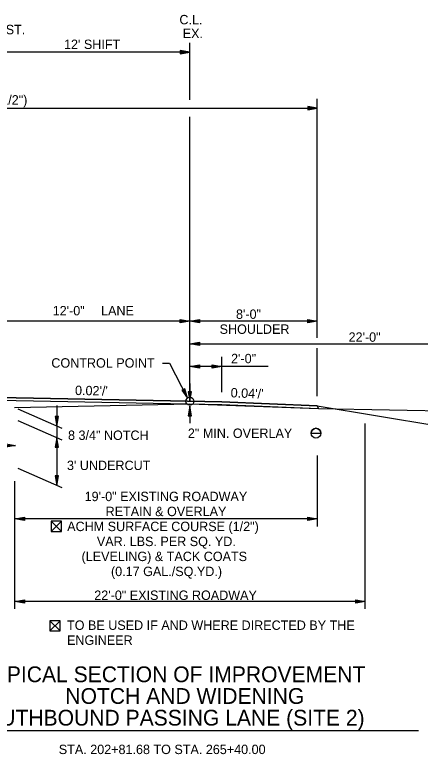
# Model space of a CAD drawing. Extents: x 1398565 to 1398920, y 1968324 to 1968581.
# Drawn here: x 1398642.8 to 1398668.26, y 1968324.76 to 1968371.14 of the extents above; entities that cross this region are included whole.
import ezdxf

# ---------------------------------------------------------------- set-up
doc = ezdxf.new("R2010")
doc.units = 0
for name, color, linetype in [('10', 7, 'Continuous'), ('19', 7, 'Continuous'), ('42', 7, 'Continuous'), ('7', 7, 'Continuous'), ('Level 9', 7, 'Continuous')]:
    doc.layers.add(name, color=color, linetype=linetype)

msp = doc.modelspace()

# ---------------------------------------------------------------- linework, layer by layer
at = {"layer": '10'}
for p, q in [((1398661.408, 1968344.894), (1398662.019, 1968344.894)), ((1398645.093, 1968339.376), (1398645.734, 1968338.735)), ((1398645.734, 1968339.376), (1398645.093, 1968338.735)), ((1398645.474, 1968338.735), (1398645.485, 1968338.735)), ((1398645.011, 1968333.13), (1398645.653, 1968332.489)), ((1398645.653, 1968333.13), (1398645.011, 1968332.489)), ((1398645.393, 1968332.489), (1398645.404, 1968332.489))]:
    msp.add_line(p, q, dxfattribs=at)
for points in [[(1398645.485, 1968338.735), (1398645.734, 1968338.735), (1398645.734, 1968339.376), (1398645.093, 1968339.376), (1398645.093, 1968338.735), (1398645.474, 1968338.735)], [(1398645.404, 1968332.489), (1398645.653, 1968332.489), (1398645.653, 1968333.13), (1398645.011, 1968333.13), (1398645.011, 1968332.489), (1398645.393, 1968332.489)]]:
    msp.add_lwpolyline(points, dxfattribs=at)
msp.add_circle((1398661.713, 1968344.894), 0.306, dxfattribs=at)
msp.add_arc((1398661.713, 1968344.894), 0.306, 0, 180, dxfattribs=at)
at = {"layer": '19'}
for p, q in [((1398653.795, 1968368.786), (1398641.795, 1968368.786)), ((1398653.195, 1968368.891), (1398653.195, 1968368.681)), ((1398653.795, 1968368.786), (1398653.195, 1968368.891)), ((1398653.635, 1968368.801), (1398653.195, 1968368.836)), ((1398653.195, 1968368.681), (1398653.795, 1968368.786)), ((1398653.195, 1968368.731), (1398653.635, 1968368.771)), ((1398661.795, 1968350.874), (1398661.795, 1968365.876)), ((1398611.795, 1968365.276), (1398661.795, 1968365.276)), ((1398661.195, 1968365.381), (1398661.195, 1968365.171)), ((1398661.795, 1968365.276), (1398661.195, 1968365.381)), ((1398661.635, 1968365.291), (1398661.195, 1968365.326)), ((1398661.195, 1968365.171), (1398661.795, 1968365.276)), ((1398661.195, 1968365.221), (1398661.635, 1968365.261)), ((1398653.195, 1968351.816), (1398653.195, 1968352.026)), ((1398653.195, 1968352.026), (1398653.795, 1968351.921)), ((1398653.795, 1968351.921), (1398654.395, 1968352.026)), ((1398654.395, 1968352.026), (1398654.395, 1968351.816)), ((1398661.195, 1968351.816), (1398661.195, 1968352.026)), ((1398661.195, 1968352.026), (1398661.795, 1968351.921)), ((1398643.795, 1968351.921), (1398631.795, 1968351.921)), ((1398661.795, 1968351.921), (1398643.795, 1968351.921)), ((1398653.195, 1968351.971), (1398653.635, 1968351.936)), ((1398653.795, 1968351.921), (1398653.195, 1968351.816)), ((1398653.635, 1968351.906), (1398653.195, 1968351.866)), ((1398654.395, 1968351.816), (1398653.795, 1968351.921)), ((1398653.955, 1968351.936), (1398654.395, 1968351.971)), ((1398654.395, 1968351.866), (1398653.955, 1968351.906)), ((1398661.195, 1968351.971), (1398661.635, 1968351.936)), ((1398661.795, 1968351.921), (1398661.195, 1968351.816)), ((1398661.635, 1968351.906), (1398661.195, 1968351.866)), ((1398653.795, 1968350.5), (1398654.395, 1968350.605)), ((1398654.395, 1968350.605), (1398654.395, 1968350.395)), ((1398653.795, 1968350.5), (1398675.795, 1968350.5)), ((1398654.395, 1968350.395), (1398653.795, 1968350.5)), ((1398653.955, 1968350.515), (1398654.395, 1968350.55)), ((1398654.395, 1968350.445), (1398653.955, 1968350.485)), ((1398661.795, 1968347.218), (1398661.795, 1968350.232)), ((1398655.795, 1968347.458), (1398655.795, 1968349.679)), ((1398653.795, 1968349.079), (1398654.395, 1968349.184)), ((1398658.72, 1968349.079), (1398653.795, 1968349.079)), ((1398654.395, 1968348.974), (1398653.795, 1968349.079)), ((1398653.955, 1968349.094), (1398654.395, 1968349.129)), ((1398654.395, 1968349.024), (1398653.955, 1968349.064)), ((1398654.395, 1968349.184), (1398654.395, 1968348.974)), ((1398655.195, 1968348.974), (1398655.195, 1968349.184)), ((1398655.195, 1968349.184), (1398655.795, 1968349.079)), ((1398655.195, 1968349.129), (1398655.635, 1968349.094)), ((1398655.795, 1968349.079), (1398655.195, 1968348.974)), ((1398655.635, 1968349.064), (1398655.195, 1968349.024)), ((1398653.795, 1968348.006), (1398653.795, 1968346.898)), ((1398653.472, 1968347.683), (1398653.286, 1968347.588)), ((1398653.286, 1968347.588), (1398653.649, 1968347.101)), ((1398653.328, 1968347.606), (1398653.563, 1968347.237)), ((1398653.587, 1968347.247), (1398653.426, 1968347.655)), ((1398653.649, 1968347.101), (1398653.472, 1968347.683)), ((1398653.9, 1968347.498), (1398653.69, 1968347.498)), ((1398653.69, 1968347.498), (1398653.795, 1968346.898)), ((1398653.745, 1968347.498), (1398653.78, 1968347.058)), ((1398653.795, 1968346.898), (1398653.9, 1968347.498)), ((1398653.81, 1968347.058), (1398653.85, 1968347.498)), ((1398641.795, 1968347.138), (1398655.795, 1968346.858)), ((1398641.795, 1968346.971), (1398655.795, 1968346.691)), ((1398643.004, 1968346.419), (1398645.747, 1968345.209)), ((1398645.444, 1968346.621), (1398645.444, 1968345.345)), ((1398653.795, 1968346.585), (1398653.69, 1968345.985)), ((1398653.78, 1968346.425), (1398653.745, 1968345.985)), ((1398653.795, 1968346.611), (1398653.795, 1968345.528)), ((1398653.9, 1968345.985), (1398653.795, 1968346.585)), ((1398653.85, 1968345.985), (1398653.81, 1968346.425)), ((1398655.795, 1968346.858), (1398661.795, 1968346.618)), ((1398655.795, 1968346.691), (1398661.88, 1968346.447)), ((1398661.795, 1968346.618), (1398675.795, 1968344.284)), ((1398661.795, 1968346.618), (1398661.88, 1968346.447)), ((1398645.549, 1968345.945), (1398645.339, 1968345.945)), ((1398645.339, 1968345.945), (1398645.444, 1968345.345)), ((1398645.394, 1968345.945), (1398645.429, 1968345.505)), ((1398645.444, 1968345.345), (1398645.549, 1968345.945)), ((1398645.459, 1968345.505), (1398645.499, 1968345.945)), ((1398653.69, 1968345.985), (1398653.9, 1968345.985)), ((1398643.004, 1968345.69), (1398645.747, 1968344.48)), ((1398664.809, 1968333.874), (1398664.809, 1968345.507)), ((1398645.444, 1968345.345), (1398645.444, 1968341.613)), ((1398645.444, 1968344.613), (1398645.339, 1968344.013)), ((1398645.549, 1968344.013), (1398645.444, 1968344.613)), ((1398645.429, 1968344.453), (1398645.394, 1968344.013)), ((1398645.499, 1968344.013), (1398645.459, 1968344.453)), ((1398645.339, 1968344.013), (1398645.549, 1968344.013)), ((1398661.795, 1968343.486), (1398661.795, 1968339.04)), ((1398643.004, 1968342.69), (1398645.747, 1968341.48)), ((1398642.809, 1968333.874), (1398642.809, 1968341.892)), ((1398645.549, 1968342.213), (1398645.339, 1968342.213)), ((1398645.339, 1968342.213), (1398645.444, 1968341.613)), ((1398645.394, 1968342.213), (1398645.429, 1968341.773)), ((1398645.444, 1968341.613), (1398645.549, 1968342.213)), ((1398645.459, 1968341.773), (1398645.499, 1968342.213)), ((1398642.809, 1968339.523), (1398643.409, 1968339.628)), ((1398643.409, 1968339.418), (1398642.809, 1968339.523)), ((1398661.795, 1968339.523), (1398642.809, 1968339.523)), ((1398642.969, 1968339.538), (1398643.409, 1968339.573)), ((1398643.409, 1968339.468), (1398642.969, 1968339.508)), ((1398643.409, 1968339.628), (1398643.409, 1968339.418)), ((1398661.195, 1968339.418), (1398661.195, 1968339.628)), ((1398661.195, 1968339.628), (1398661.795, 1968339.523)), ((1398661.195, 1968339.573), (1398661.635, 1968339.538)), ((1398661.795, 1968339.523), (1398661.195, 1968339.418)), ((1398661.635, 1968339.508), (1398661.195, 1968339.468)), ((1398642.809, 1968334.343), (1398643.409, 1968334.448)), ((1398642.969, 1968334.358), (1398643.409, 1968334.393)), ((1398643.409, 1968334.448), (1398643.409, 1968334.238)), ((1398664.209, 1968334.238), (1398664.209, 1968334.448)), ((1398664.209, 1968334.448), (1398664.809, 1968334.343)), ((1398664.209, 1968334.393), (1398664.649, 1968334.358)), ((1398664.809, 1968334.343), (1398642.809, 1968334.343)), ((1398643.409, 1968334.238), (1398642.809, 1968334.343)), ((1398643.409, 1968334.288), (1398642.969, 1968334.328)), ((1398664.809, 1968334.343), (1398664.209, 1968334.238)), ((1398664.649, 1968334.328), (1398664.209, 1968334.288)), ((1398639.176, 1968326.249), (1398668.156, 1968326.249))]:
    msp.add_line(p, q, dxfattribs=at)
msp.add_lwpolyline([(1398652.07, 1968349.278), (1398652.516, 1968349.278), (1398653.649, 1968347.101)], dxfattribs=at)
msp.add_lwpolyline([(1398611.71, 1968346.287), (1398615.795, 1968346.451), (1398641.795, 1968346.971), (1398655.795, 1968346.691), (1398661.88, 1968346.447), (1398661.795, 1968346.618), (1398655.795, 1968346.858), (1398641.795, 1968347.138), (1398615.795, 1968346.618), (1398611.795, 1968346.458)], close=True, dxfattribs=at)
at = {"layer": '42'}
for p, q in [((1398640.747, 1968344.124), (1398642.842, 1968344.124)), ((1398642.242, 1968344.229), (1398642.842, 1968344.124)), ((1398642.842, 1968344.124), (1398642.242, 1968344.019))]:
    msp.add_line(p, q, dxfattribs=at)
for points in [[(1398642.795, 1968346.511), (1398653.795, 1968346.731)], [(1398653.795, 1968346.731), (1398661.88, 1968346.447), (1398670.795, 1968346.271), (1398679.65, 1968343.81), (1398684.731, 1968344.352), (1398701.547, 1968344.263)]]:
    msp.add_lwpolyline(points, dxfattribs=at)
at = {"layer": '7'}
for p, q in [((1398653.795, 1968365.811), (1398653.795, 1968369.386)), ((1398653.795, 1968347.138), (1398653.795, 1968364.745))]:
    msp.add_line(p, q, dxfattribs=at)
at = {"layer": 'Level 9'}
msp.add_circle((1398653.795, 1968346.898), 0.25, dxfattribs=at)

# ---------------------------------------------------------------- texts
at = {"layer": '10'}
for s, height, p in [('12\'-0" ', 0.59, (1398645.183, 1968352.284)), ('LANE', 0.59, (1398648.221, 1968352.284)), ('8\'-0" ', 0.59, (1398656.691, 1968352.066)), ('SHOULDER', 0.59, (1398655.664, 1968351.126)), ('22\'-0"', 0.59, (1398663.759, 1968350.628)), ('2\'-0"', 0.59, (1398656.383, 1968349.282)), ('CONTROL POINT', 0.59001, (1398645.099, 1968349.006)), ('8 3/4" NOTCH', 0.59001, (1398646.146, 1968344.471)), ('2" MIN. OVERLAY', 0.59001, (1398653.671, 1968344.597)), ("3' UNDERCUT", 0.59001, (1398646.079, 1968342.583)), ('19\'-0" EXISTING ROADWAY', 0.59001, (1398647.189, 1968340.631)), ('RETAIN & OVERLAY', 0.59001, (1398648.504, 1968339.691)), ('ACHM SURFACE COURSE (1/2")', 0.59001, (1398646.093, 1968338.751)), ('VAR. LBS. PER SQ. YD.', 0.59001, (1398647.956, 1968337.811)), ('(LEVELING) & TACK COATS', 0.59001, (1398646.994, 1968336.871)), ('(0.17 GAL./SQ.YD.)', 0.59001, (1398648.843, 1968335.931)), ('22\'-0" EXISTING ROADWAY', 0.59001, (1398647.794, 1968334.435)), ('TO BE USED IF AND WHERE DIRECTED BY THE ', 0.59001, (1398646.084, 1968332.556)), ('ENGINEER', 0.59, (1398646.084, 1968331.616)), ('STA. 202+81.68 TO STA. 265+40.00', 0.59001, (1398645.566, 1968324.765))]:
    msp.add_text(s, height=height, rotation=360, dxfattribs=at).set_placement(p)
at = {"layer": '19'}
msp.add_text('C.L.', height=0.59, dxfattribs=at).set_placement((1398653.14, 1968370.541))
for s, height, rotation, p in [('CONST.', 0.59, 360, (1398640.481, 1968369.92)), ('EX.', 0.59, 360, (1398653.345, 1968369.674)), ("12' SHIFT", 0.59, 360, (1398645.895, 1968368.993)), ("0.02'/'", 0.59, 358.8542, (1398646.581, 1968347.291)), ("0.04'/'", 0.59, 357.7094, (1398656.347, 1968347.147)), ('TYPICAL SECTION OF IMPROVEMENT', 0.98999, 360, (1398640.613, 1968329.275)), ('NOTCH AND WIDENING', 0.98999, 360, (1398645.976, 1968327.914)), ('SOUTHBOUND PASSING LANE (SITE 2)', 0.98999, 360, (1398639.977, 1968326.553))]:
    msp.add_text(s, height=height, rotation=rotation, dxfattribs=at).set_placement(p)
at = {"layer": '42'}
msp.add_text('50\'-0" ACHM SURFACE COURSE (1/2")', height=0.59001, rotation=360, dxfattribs=at).set_placement((1398629.336, 1968365.507))

doc.saveas('drawing.dxf')
